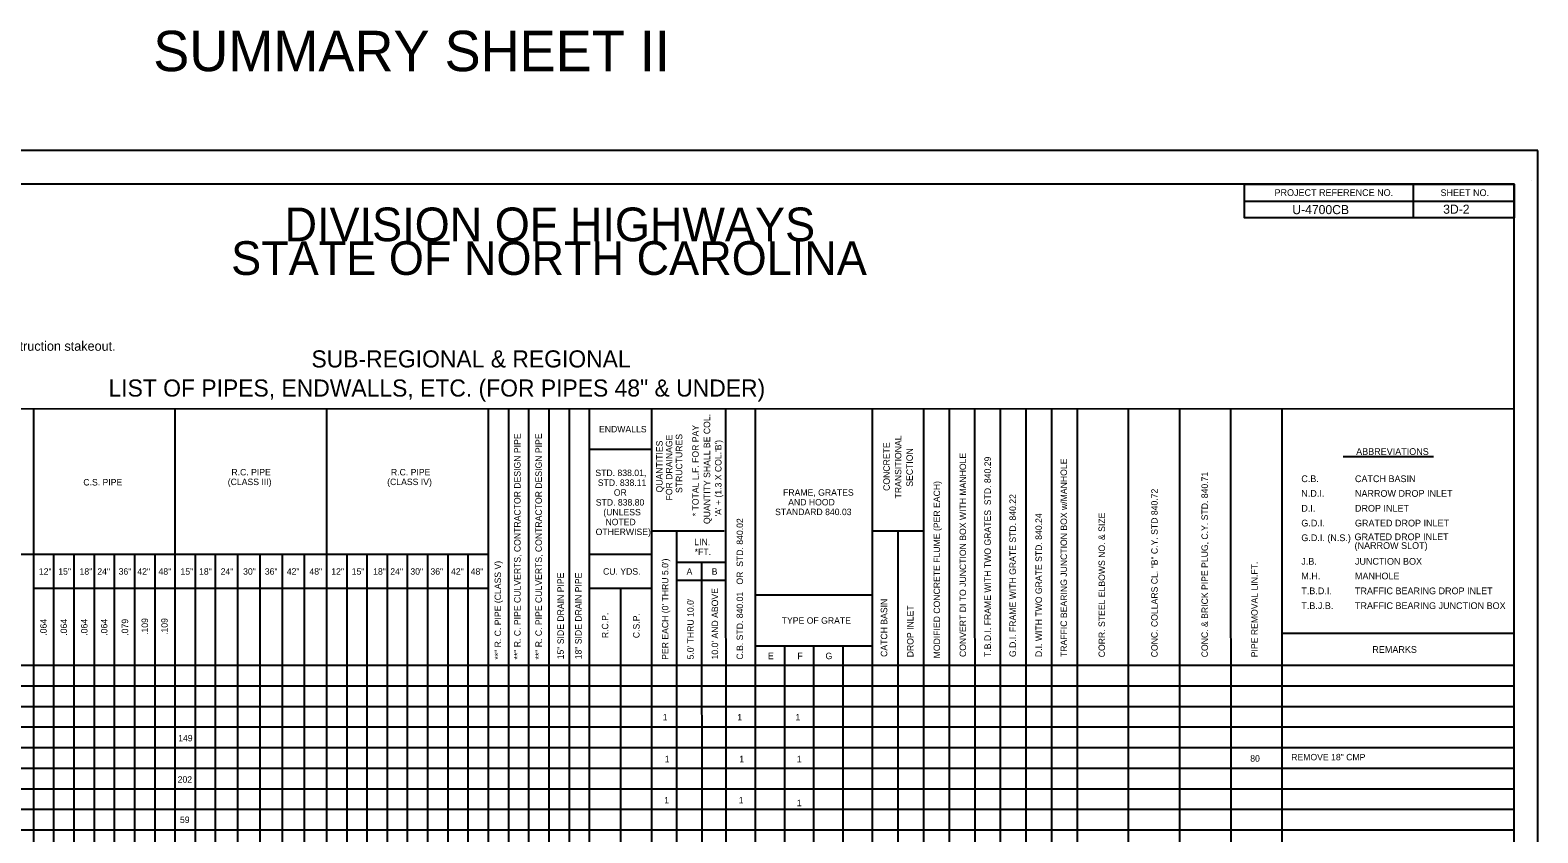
# Model space of a CAD drawing. Extents: x 809447 to 814738, y 647528 to 651206.
# Drawn here: x 811820 to 812939, y 650610 to 651206 of the extents above; entities that cross this region are included whole.
import ezdxf

# ---------------------------------------------------------------- set-up
doc = ezdxf.new("R2010")
doc.units = 0
doc.layers.add('Default', color=7, linetype='Continuous')
doc.layers.add('Old_Level_44', color=7, linetype='Continuous')

msp = doc.modelspace()

# ---------------------------------------------------------------- linework, layer by layer
at = {"layer": 'Default'}
for p, q in [((812846.2, 651091.9), (812846.2, 651066.9)), ((812933.7, 651094.5), (812933.7, 651094.5)), ((812933.7, 651094.5), (812933.7, 651094.5)), ((812933.7, 651094.5), (812933.7, 651094.5)), ((812721.1, 651079.4), (812921.2, 651079.4)), ((812921.2, 650925.1), (811421.2, 650925)), ((811822.5, 650154.3), (811822.5, 650925)), ((811927.5, 650154.3), (811927.5, 650925)), ((812040.1, 650154.3), (812040, 650925.1)), ((812160.1, 650154.3), (812160, 650925.1)), ((812175.1, 650154.3), (812175, 650925.1)), ((812190.1, 650154.3), (812190, 650925.1)), ((812205.1, 650154.3), (812205, 650925.1)), ((812220.1, 650154.3), (812220, 650925.1)), ((812235.1, 650154.3), (812235, 650925.1)), ((812235, 650154.3), (812235, 650925.1)), ((812235.1, 650154.3), (812235, 650925.1)), ((812281.3, 650154.3), (812281.2, 650925)), ((812336.3, 650154.3), (812336.2, 650925)), ((812336.3, 650154.3), (812336.2, 650925)), ((812358.1, 650154.3), (812358.1, 650925)), ((812445.1, 650154.3), (812445, 650925)), ((812483.1, 650154.3), (812483, 650925)), ((812502.1, 650154.3), (812502, 650925)), ((812521.1, 650154.3), (812521, 650925)), ((812540.1, 650154.3), (812540, 650925)), ((812559.1, 650154.3), (812559, 650925)), ((812578.1, 650154.3), (812578, 650925)), ((812597.1, 650154.3), (812597, 650925)), ((812635.1, 650154.3), (812635, 650925)), ((812635.1, 650154.3), (812635, 650925)), ((812673.1, 650154.3), (812673, 650925)), ((812673.1, 650154.3), (812673, 650925)), ((812711.1, 650154.3), (812711, 650925)), ((812711.1, 650154.3), (812711, 650925)), ((812749.1, 650154.3), (812749, 650925)), ((812749.1, 650154.3), (812749, 650925)), ((812281.2, 650895.1), (812235, 650895.1)), ((812861.3, 650889.6), (812794.3, 650889.6)), ((812335, 650834.3), (812281.2, 650834.3)), ((812299.9, 650154.3), (812299.8, 650834.3)), ((812483, 650834.3), (812445, 650834.3)), ((812464.1, 650154.3), (812464, 650834.3)), ((812160, 650817.2), (811642.5, 650817.1)), ((811837.5, 650154.3), (811837.5, 650817.1)), ((811852.5, 650154.3), (811852.5, 650817.2)), ((811867.5, 650154.3), (811867.5, 650817.1)), ((811882.5, 650154.3), (811882.5, 650817.2)), ((811897.5, 650154.3), (811897.5, 650817.1)), ((811912.5, 650154.3), (811912.5, 650817.2)), ((811927.5, 650154.3), (811927.5, 650817.1)), ((811942.5, 650154.3), (811942.5, 650817.2)), ((811957.5, 650154.3), (811957.5, 650817.2)), ((811974, 650154.3), (811974, 650817.2)), ((811990.5, 650154.3), (811990.5, 650817.2)), ((812007, 650154.3), (812007, 650817.2)), ((812023.5, 650154.3), (812023.5, 650817.2)), ((812040, 650154.3), (812040, 650817.2)), ((812055, 650154.3), (812055, 650817.2)), ((812070, 650154.3), (812070, 650817.2)), ((812085, 650154.3), (812085, 650817.2)), ((812100, 650154.3), (812100, 650817.2)), ((812115, 650154.3), (812115, 650817.2)), ((812130, 650154.3), (812130, 650817.2)), ((812145, 650154.3), (812145, 650817.2)), ((812160, 650154.3), (812160, 650817.2)), ((812281.2, 650817.2), (812235, 650817.2)), ((812336.2, 650811.1), (812299.8, 650811.1)), ((812318.5, 650154.3), (812318.4, 650811.1)), ((812160, 650791.8), (811822.5, 650791.8)), ((811822.5, 650154.3), (811822.5, 650791.8)), ((812281.2, 650791.8), (812235, 650791.8)), ((812258.2, 650154.3), (812258.1, 650791.8)), ((812336.2, 650797.9), (812299.8, 650797.9)), ((812445, 650786.8), (812358.1, 650786.8)), ((812921.2, 650758.5), (812749, 650758.5)), ((812445, 650749), (812358.1, 650749)), ((812379.9, 650154.3), (812379.8, 650749)), ((812401.6, 650154.3), (812401.5, 650749)), ((812423.3, 650154.3), (812423.3, 650749)), ((812921.2, 650734.7), (811421.2, 650734.7)), ((812921.2, 650719.4), (811421.2, 650719.4)), ((812921.2, 650704.1), (811421.2, 650704.1)), ((812921.2, 650688.9), (811421.2, 650688.9)), ((812921.2, 650673.6), (811421.2, 650673.6)), ((812921.2, 650658.3), (811421.2, 650658.3)), ((812921.2, 650643), (811421.2, 650643)), ((812921.2, 650627.8), (811421.2, 650627.8)), ((812921.2, 650612.5), (811421.2, 650612.5))]:
    msp.add_line(p, q, dxfattribs=at)
for points in [[(812938.7, 651116.9), (811254.7, 651116.9), (811254.7, 650016.9), (812938.7, 650016.9)], [(812921.2, 651091.9), (811421.2, 651091.9), (811421.2, 650041.9), (812921.2, 650041.9)], [(812721.1, 651091.9), (812921.2, 651091.9), (812921.2, 651066.9), (812721.1, 651066.9)]]:
    msp.add_lwpolyline(points, close=True, dxfattribs=at)

# ---------------------------------------------------------------- texts
for s, height, rotation, p in [('PROJECT REFERENCE NO.', 5, 360, (812743.3, 651083.2)), ('SHEET NO.', 5, 360, (812866.5, 651083.1)), ('DIVISION OF HIGHWAYS', 25, 360, (812008.6, 651049.6)), ('U-4700CB', 6.75, 360, (812756.5, 651069.7)), ('3D-2', 6.75, 360, (812868.5, 651070)), ('STATE OF NORTH CAROLINA', 25, 360, (811969, 651024.6)), ('* TOTAL L.F. FOR PAY', 4.8, 90, (812316, 650845.5)), ('QUANTITY SHALL BE COL.', 4.8, 90, (812324.5, 650839.7)), ('**" R. C. PIPE CULVERTS, CONTRACTOR DESIGN PIPE', 4.8, 90, (812183.8, 650739.2)), ('**" R. C. PIPE CULVERTS, CONTRACTOR DESIGN PIPE', 4.8, 90, (812199.6, 650739.2)), ('QUANTITIES', 4.8, 90, (812289.2, 650863.1)), ('FOR DRAINAGE', 4.8, 90, (812296.4, 650857.2)), ('STRUCTURES', 4.8, 90, (812303.8, 650862.7)), ("'A' + (1.3 X COL.'B')", 4.8, 90, (812332.9, 650845.3)), ('CONCRETE', 4.8, 90, (812457.8, 650864.3)), ('TRANSITIONAL', 4.8, 90, (812466.4, 650858.7)), ('SECTION', 4.8, 90, (812474.9, 650867.4)), ('CONVERT DI TO JUNCTION BOX WITH MANHOLE', 4.8, 90, (812514.4, 650741)), ('T.B.D.I. FRAME WITH TWO GRATES  STD. 840.29', 4.8, 90, (812532.8, 650741)), ('TRAFFIC BEARING JUNCTION BOX w/MANHOLE', 4.8, 90, (812589.3, 650741)), ('CONC. & BRICK PIPE PLUG, C.Y. STD. 840.71', 4.8, 90, (812693.9, 650740.8)), ('MODIFIED CONCRETE FLUME (PER EACH)', 4.8, 90, (812495.1, 650740)), ('CONC. COLLARS CL. "B" C.Y. STD 840.72', 4.8, 90, (812656.6, 650740.8)), ('G.D.I. FRAME WITH GRATE STD. 840.22', 4.8, 90, (812551.4, 650741)), ('C.B. STD. 840.01   OR  STD. 840.02', 4.8, 90, (812348.9, 650739.1)), ('D.I. WITH TWO GRATE STD. 840.24', 4.8, 90, (812570.7, 650741)), ('CORR. STEEL ELBOWS NO. & SIZE', 4.8, 90, (812617.5, 650740.8)), ('GRATED DROP INLET', 5, 0.0274, (812802.7, 650827.7)), ('(NARROW SLOT)', 5, 0.0274, (812802.7, 650821.2)), ('**" R. C. PIPE (CLASS V)', 4.8, 90, (812169.3, 650739.1)), ("PER EACH (0' THRU 5.0')", 4.799, 90.0369, (812293.5, 650738.9)), ('PIPE REMOVAL LIN.FT.', 4.8, 90, (812730.8, 650740.8)), ('15" SIDE DRAIN PIPE', 4.8, 90, (812215.9, 650739.3)), ('18" SIDE DRAIN PIPE', 4.8, 90, (812229.1, 650739.3)), ("10.0' AND ABOVE", 4.8, 90, (812330.4, 650739.2)), ("5.0' THRU 10.0'", 4.8, 90, (812312.3, 650739.2)), ('CATCH BASIN', 4.8, 90, (812455.9, 650741.1)), ('DROP INLET', 4.8, 90, (812475.4, 650740.8)), ('.064', 4.8, 90, (811832.1, 650756.8)), ('.064', 4.8, 90, (811847.2, 650756.8)), ('.064', 4.8, 90, (811862.4, 650756.8)), ('.064', 4.8, 90, (811877.2, 650756.8)), ('.079', 4.8, 90, (811892.6, 650756.8)), ('.109', 4.8, 90, (811907.3, 650757.4)), ('.109', 4.8, 90, (811921.9, 650757.4)), ('R.C.P.', 4.8, 90, (812248.9, 650755)), ('C.S.P.', 4.8, 90, (812272.1, 650755))]:
    msp.add_text(s, height=height, rotation=rotation, dxfattribs=at).set_placement(p)
for s, height, p in [('NOTE: Invert Elevations are for Bid Purposes only and shall not be used for project construction stakeout.', 7, (811445.7, 650968.3)), ('SUB-REGIONAL & REGIONAL', 12.7, (812028.6, 650955.9)), ('LIST OF PIPES, ENDWALLS, ETC. (FOR PIPES 48" & UNDER)', 12.7, (811878, 650934.3)), ('ENDWALLS', 4.8, (812242, 650907.7)), ('ABBREVIATIONS', 5, (812803.9, 650891)), ('R.C. PIPE', 4.8, (811969.2, 650875.8)), ('R.C. PIPE', 4.8, (812087.6, 650875.8)), ('STD. 838.01,', 4.8, (812239.3, 650875.3)), ('C.S. PIPE', 4.8, (811859.3, 650868.3)), ('(CLASS III)', 4.8, (811966.5, 650868.6)), ('(CLASS IV)', 4.8, (812084.8, 650868.6)), ('STD. 838.11', 4.8, (812241.1, 650868)), ('FRAME, GRATES', 4.8, (812378.6, 650860.7)), ('C.B.', 5, (812763.2, 650870.8)), ('CATCH BASIN', 5, (812803, 650870.8)), ('STD. 838.80', 4.8, (812239.6, 650853.4)), ('OR', 4.8, (812253, 650860.7)), ('AND HOOD', 4.8, (812382.4, 650853.5)), ('N.D.I.', 5, (812763.2, 650859.9)), ('NARROW DROP INLET', 5, (812803, 650859.9)), ('(UNLESS', 4.8, (812245.2, 650846.1)), ('NOTED', 4.8, (812246.8, 650838.8)), ('STANDARD 840.03', 4.8, (812372.7, 650846.3)), ('D.I.', 5, (812763.2, 650848.9)), ('DROP INLET', 5, (812803, 650848.9)), ('OTHERWISE)', 4.8, (812239.5, 650831.5)), ('G.D.I.', 5, (812763.2, 650837.9)), ('G.D.I. (N.S.)', 5, (812763.2, 650827)), ('GRATED DROP INLET', 5, (812803, 650837.9)), ('*FT.', 4.8, (812313, 650816.7)), ('LIN.', 4.8, (812312.7, 650824)), ('J.B.', 5, (812763.2, 650809.5)), ('JUNCTION BOX', 5, (812803, 650809.5)), ('12"', 4.8, (811826.3, 650802.1)), ('15"', 4.8, (811840.7, 650802.1)), ('18"', 4.8, (811856.5, 650802.1)), ('24"', 4.8, (811869.7, 650802.1)), ('36"', 4.8, (811885.5, 650802.1)), ('42"', 4.8, (811899.4, 650802.1)), ('48"', 4.8, (811915.1, 650802.1)), ('15"', 4.8, (811931.4, 650802.1)), ('18"', 4.8, (811945.2, 650802.1)), ('24"', 4.8, (811961.2, 650802.1)), ('30"', 4.8, (811977.9, 650802.1)), ('36"', 4.8, (811994, 650802.1)), ('42"', 4.8, (812010.3, 650802.1)), ('48"', 4.8, (812027.1, 650802.1)), ('12"', 4.8, (812043.3, 650802.1)), ('15"', 4.8, (812058.5, 650802.1)), ('18"', 4.8, (812074.4, 650802.1)), ('24"', 4.8, (812087.1, 650802.1)), ('30"', 4.8, (812102, 650802.1)), ('36"', 4.8, (812116.9, 650802.1)), ('42"', 4.8, (812132.2, 650802.1)), ('48"', 4.8, (812146.8, 650802.1)), ('CU. YDS.', 4.8, (812245, 650802.1)), ('A', 4.8, (812307, 650802.1)), ('B', 4.8, (812325.6, 650802.1)), ('M.H.', 5, (812763.2, 650798.6)), ('MANHOLE', 5, (812803, 650798.6)), ('T.B.D.I.', 5, (812763.2, 650787.6)), ('TRAFFIC BEARING DROP INLET', 5, (812803, 650787.6)), ('T.B.J.B.', 5, (812763.2, 650776.6)), ('TRAFFIC BEARING JUNCTION BOX', 5, (812803, 650776.6)), ('TYPE OF GRATE', 4.8, (812377.6, 650765.7)), ('E', 4.8, (812367.4, 650739.4)), ('F', 4.8, (812389.2, 650739.4)), ('G', 4.8, (812410.1, 650739.4)), ('REMARKS', 5, (812815.9, 650744.1)), ('1', 4.8, (812289.3, 650693.9)), ('1', 4.8, (812344.6, 650693.9)), ('1', 4.8, (812387.8, 650693.9)), ('149', 4.8, (811929.7, 650678.4)), ('1', 4.8, (812290.8, 650662.9)), ('1', 4.8, (812346.1, 650662.9)), ('1', 4.8, (812388.8, 650662.9)), ('80', 4.8, (812725.3, 650663.3)), ('REMOVE 18" CMP', 4.8, (812755.7, 650664.3)), ('202', 4.8, (811929.3, 650647.7)), ('1', 4.8, (812290.4, 650632.3)), ('1', 4.8, (812345.7, 650632.3)), ('1', 4.8, (812388.8, 650630.3)), ('59', 4.8, (811931, 650617.8))]:
    msp.add_text(s, height=height, dxfattribs=at).set_placement(p)
at = {"layer": 'Old_Level_44'}
msp.add_text('SUMMARY SHEET II', height=30, rotation=360, dxfattribs=at).set_placement((811911.2, 651175.8))

doc.saveas('drawing.dxf')
